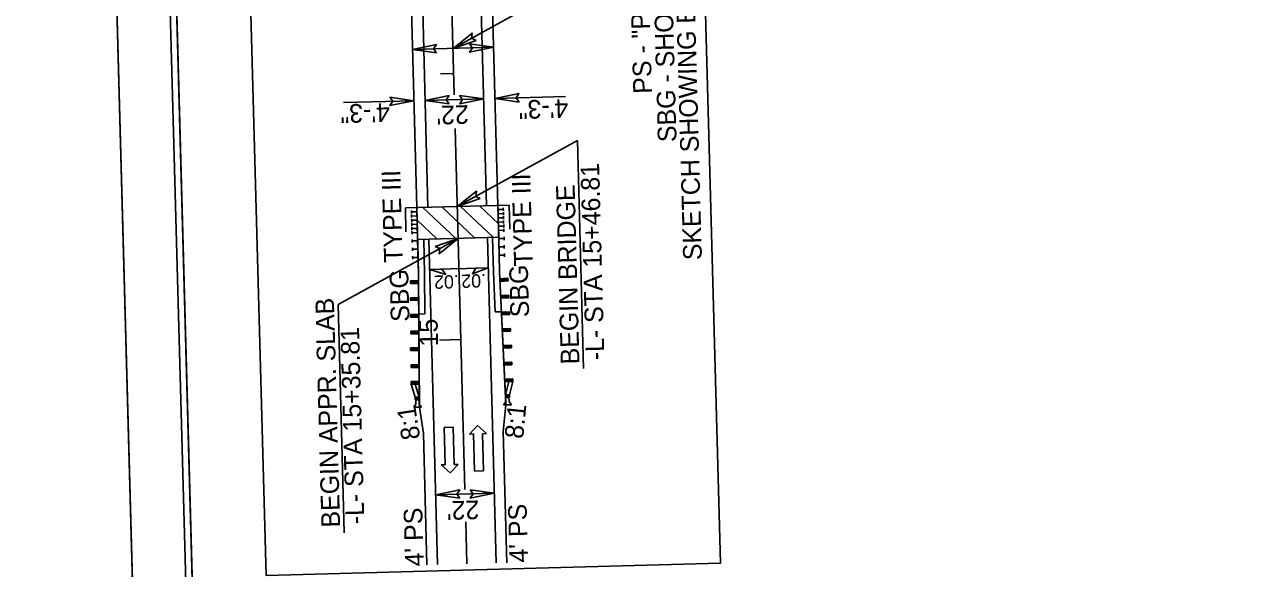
# Model space of a CAD drawing. Extents: x 1835283 to 1836442, y 993567 to 997230.
# Drawn here: x 1835301.2 to 1835759.8, y 993870.9 to 994075.4 of the extents above; entities that cross this region are included whole.
import ezdxf

# ---------------------------------------------------------------- set-up
doc = ezdxf.new("R2010")
doc.units = 0
for name, color, linetype in [('Prop Approach Slab', 7, 'Continuous'), ('Prop Approach Slab Hatching', 7, 'Continuous'), ('Prop Dimension', 7, 'Continuous'), ('Prop EOT', 7, 'Continuous'), ('Prop Guardrail', 7, 'Continuous'), ('Prop Guardrail Anchor Unit CELL', 7, 'Continuous'), ('Prop Horizontal Alignment', 7, 'Continuous'), ('Prop Horizontal Alignment Tick Label', 7, 'Continuous'), ('Prop Horizontal Alignment Tick Large', 7, 'Continuous'), ('Prop Horizontal Alignment Tick Small', 7, 'Continuous'), ('Prop Lane Arrow CELL', 7, 'Continuous'), ('Prop Lane Lines', 7, 'Continuous'), ('Prop Paved Shoulder', 7, 'Continuous'), ('Prop Roadway Bridge', 7, 'Continuous'), ('Prop SBG', 7, 'Continuous'), ('Prop Structure Anchor Unit CELL', 7, 'Continuous'), ('Prop Superelevation  Arrow CELL', 7, 'Continuous'), ('Prop Terminator CELL', 7, 'Continuous'), ('Sheet Clip Boundary CELL', 7, 'Continuous'), ('Sheet Cutting Line CELL', 7, 'Continuous'), ('Sheet Layout Plan Border', 7, 'Continuous'), ('Sheet Plan CELL', 7, 'Continuous'), ('Sheet Plan Layout CELL', 7, 'Continuous'), ('Sheet Plot Border Inside CELL', 7, 'Continuous'), ('Sheet Plot Border Outside CELL', 7, 'Continuous')]:
    doc.layers.add(name, color=color, linetype=linetype)

msp = doc.modelspace()

# ---------------------------------------------------------------- linework, layer by layer
at = {"layer": 'Prop Approach Slab'}
for p, q in [((1835448.84, 993994.6), (1835448.52, 994006.6)), ((1835479.33, 993995.42), (1835479.01, 994007.41)), ((1835479.33, 993995.42), (1835448.84, 993994.6))]:
    msp.add_line(p, q, dxfattribs=at)
at = {"layer": 'Prop Approach Slab Hatching'}
for p, q in [((1835450.85, 994006.66), (1835463.2, 993994.99)), ((1835457.93, 994006.85), (1835470.28, 993995.18)), ((1835465.01, 994007.04), (1835477.36, 993995.37)), ((1835472.09, 994007.23), (1835479.2, 994000.51)), ((1835448.65, 994001.86), (1835456.12, 993994.8))]:
    msp.add_line(p, q, dxfattribs=at)
at = {"layer": 'Prop Dimension'}
for p, q in [((1835462.17, 994066.44), (1835494.43, 994084.16)), ((1835477.42, 994066.84), (1835446.93, 994066.03)), ((1835504.36, 994048.28), (1835477.94, 994047.57)), ((1835447.45, 994046.75), (1835421.03, 994046.05)), ((1835473.69, 994047.46), (1835451.69, 994046.87)), ((1835508.87, 994031.8), (1835463.77, 994007.01)), ((1835511.21, 993946.11), (1835508.87, 994031.8)), ((1835464.09, 993995.01), (1835418.99, 993970.21)), ((1835421.33, 993884.43), (1835418.99, 993970.21)), ((1835477.65, 993899.27), (1835455.66, 993898.68))]:
    msp.add_line(p, q, dxfattribs=at)
msp.add_lwpolyline([(1835549.77, 994346.04), (1835562.69, 993873.01), (1835392.04, 993868.35), (1835379.12, 994341.38)], close=True, dxfattribs=at)
at = {"layer": 'Prop EOT'}
for p, q in [((1835456.36, 993872.46), (1835453.09, 993994.72)), ((1835478.36, 993873.05), (1835475.08, 993995.31))]:
    msp.add_line(p, q, dxfattribs=at)
at = {"layer": 'Prop Guardrail'}
msp.add_line((1835449.02, 993987.86), (1835449.19, 993981.61), dxfattribs=at)
msp.add_lwpolyline([(1835479.68, 993982.42), (1835479.51, 993988.67)], dxfattribs=at)
at = {"layer": 'Prop Guardrail Anchor Unit CELL'}
for p, q in [((1835449.21, 993979.06), (1835446.21, 993979.04)), ((1835447.71, 993978.05), (1835446.21, 993979.04)), ((1835446.21, 993979.04), (1835446.22, 993978.04)), ((1835446.22, 993978.04), (1835447.71, 993979.05)), ((1835447.71, 993978.05), (1835449.21, 993979.06)), ((1835447.71, 993979.05), (1835447.71, 993978.05)), ((1835447.71, 993979.05), (1835449.21, 993978.06)), ((1835449.19, 993981.61), (1835449.51, 993934.86)), ((1835449.21, 993979.06), (1835449.21, 993978.06)), ((1835479.68, 993982.42), (1835481.87, 993935.72)), ((1835479.8, 993979.88), (1835482.79, 993980.02)), ((1835479.8, 993979.88), (1835479.85, 993978.89)), ((1835481.34, 993978.96), (1835479.8, 993979.88)), ((1835481.3, 993979.95), (1835479.85, 993978.89)), ((1835479.85, 993978.89), (1835482.84, 993979.03)), ((1835479.85, 993978.89), (1835481.34, 993978.96)), ((1835481.3, 993979.95), (1835481.34, 993978.96)), ((1835482.84, 993979.03), (1835481.3, 993979.95)), ((1835481.34, 993978.96), (1835482.79, 993980.02)), ((1835482.79, 993980.02), (1835482.84, 993979.03)), ((1835449.21, 993978.06), (1835446.22, 993978.04)), ((1835449.21, 993978.06), (1835447.71, 993978.05)), ((1835449.25, 993972.76), (1835446.2, 993972.74)), ((1835446.2, 993971.74), (1835447.72, 993972.75)), ((1835447.73, 993971.75), (1835446.2, 993972.74)), ((1835446.2, 993972.74), (1835446.2, 993971.74)), ((1835449.26, 993971.76), (1835446.2, 993971.74)), ((1835447.72, 993972.75), (1835447.73, 993971.75)), ((1835447.72, 993972.75), (1835449.26, 993971.76)), ((1835449.25, 993972.76), (1835447.73, 993971.75)), ((1835480.09, 993973.59), (1835483.14, 993973.73)), ((1835480.09, 993973.59), (1835481.66, 993972.66)), ((1835481.62, 993973.66), (1835480.14, 993972.59)), ((1835480.14, 993972.59), (1835483.19, 993972.73)), ((1835481.62, 993973.66), (1835481.66, 993972.66)), ((1835483.19, 993972.73), (1835481.62, 993973.66)), ((1835481.66, 993972.66), (1835483.14, 993973.73)), ((1835483.14, 993973.73), (1835483.19, 993972.73)), ((1835449.29, 993966.46), (1835446.25, 993966.44)), ((1835446.25, 993965.44), (1835447.77, 993966.45)), ((1835447.78, 993965.45), (1835446.25, 993966.44)), ((1835446.25, 993966.44), (1835446.25, 993965.44)), ((1835449.3, 993965.46), (1835446.25, 993965.44)), ((1835447.77, 993966.45), (1835447.78, 993965.45)), ((1835447.77, 993966.45), (1835449.3, 993965.46)), ((1835449.29, 993966.46), (1835447.78, 993965.45)), ((1835480.39, 993967.3), (1835483.43, 993967.44)), ((1835480.39, 993967.3), (1835481.96, 993966.37)), ((1835481.91, 993967.37), (1835480.43, 993966.3)), ((1835480.43, 993966.3), (1835483.48, 993966.44)), ((1835481.91, 993967.37), (1835481.96, 993966.37)), ((1835483.48, 993966.44), (1835481.91, 993967.37)), ((1835481.96, 993966.37), (1835483.43, 993967.44)), ((1835483.43, 993967.44), (1835483.48, 993966.44)), ((1835480.68, 993961), (1835483.71, 993961.14)), ((1835480.68, 993961), (1835480.73, 993960)), ((1835480.68, 993961), (1835482.25, 993960.07)), ((1835482.2, 993961.07), (1835480.73, 993960)), ((1835482.2, 993961.07), (1835482.25, 993960.07)), ((1835483.76, 993960.14), (1835482.2, 993961.07)), ((1835482.25, 993960.07), (1835483.71, 993961.14)), ((1835483.71, 993961.14), (1835483.76, 993960.14)), ((1835449.34, 993960.16), (1835446.3, 993960.14)), ((1835447.82, 993959.15), (1835446.3, 993960.14)), ((1835446.3, 993960.14), (1835446.31, 993959.14)), ((1835446.31, 993959.14), (1835447.82, 993960.15)), ((1835449.34, 993959.16), (1835446.31, 993959.14)), ((1835449.34, 993960.16), (1835447.82, 993959.15)), ((1835447.82, 993960.15), (1835447.82, 993959.15)), ((1835447.82, 993960.15), (1835449.34, 993959.16)), ((1835449.34, 993960.16), (1835449.34, 993959.16)), ((1835480.73, 993960), (1835483.76, 993960.14)), ((1835449.38, 993953.86), (1835446.24, 993953.84)), ((1835447.82, 993952.85), (1835446.24, 993953.84)), ((1835446.24, 993953.84), (1835446.25, 993952.84)), ((1835446.25, 993952.84), (1835447.81, 993953.85)), ((1835449.39, 993952.86), (1835446.25, 993952.84)), ((1835447.81, 993953.85), (1835447.82, 993952.85)), ((1835447.81, 993953.85), (1835449.39, 993952.86)), ((1835449.38, 993953.86), (1835447.82, 993952.85)), ((1835480.98, 993954.71), (1835484.11, 993954.85)), ((1835480.98, 993954.71), (1835482.59, 993953.78)), ((1835482.54, 993954.78), (1835481.02, 993953.71)), ((1835481.02, 993953.71), (1835484.16, 993953.85)), ((1835482.54, 993954.78), (1835482.59, 993953.78)), ((1835484.16, 993953.85), (1835482.54, 993954.78)), ((1835482.59, 993953.78), (1835484.11, 993954.85)), ((1835484.11, 993954.85), (1835484.16, 993953.85)), ((1835449.42, 993947.56), (1835446.42, 993947.54)), ((1835447.93, 993946.55), (1835446.42, 993947.54)), ((1835446.42, 993947.54), (1835446.43, 993946.54)), ((1835446.43, 993946.54), (1835447.92, 993947.55)), ((1835447.92, 993947.55), (1835447.93, 993946.55)), ((1835447.92, 993947.55), (1835449.43, 993946.56)), ((1835449.42, 993947.56), (1835447.93, 993946.55)), ((1835481.27, 993948.41), (1835484.27, 993948.55)), ((1835481.27, 993948.41), (1835482.82, 993947.48)), ((1835482.77, 993948.48), (1835481.32, 993947.41)), ((1835481.32, 993947.41), (1835484.31, 993947.55)), ((1835482.77, 993948.48), (1835482.82, 993947.48)), ((1835484.31, 993947.55), (1835482.77, 993948.48)), ((1835482.82, 993947.48), (1835484.27, 993948.55)), ((1835484.27, 993948.55), (1835484.31, 993947.55)), ((1835449.43, 993946.56), (1835446.43, 993946.54)), ((1835481.57, 993942.12), (1835484.63, 993942.26)), ((1835483.1, 993942.19), (1835481.61, 993941.12)), ((1835483.1, 993942.19), (1835483.14, 993941.19)), ((1835484.67, 993941.26), (1835483.1, 993942.19)), ((1835483.14, 993941.19), (1835484.63, 993942.26)), ((1835484.63, 993942.26), (1835484.67, 993941.26)), ((1835449.46, 993941.26), (1835446.4, 993941.24)), ((1835447.94, 993940.25), (1835446.4, 993941.24)), ((1835446.4, 993941.24), (1835446.41, 993940.24)), ((1835446.41, 993940.24), (1835447.93, 993941.25)), ((1835449.47, 993940.26), (1835446.41, 993940.24)), ((1835446.41, 993940.24), (1835448, 993935.35)), ((1835447.93, 993941.25), (1835447.94, 993940.25)), ((1835447.93, 993941.25), (1835449.47, 993940.26)), ((1835449.46, 993941.26), (1835447.94, 993940.25)), ((1835447.94, 993940.25), (1835449.5, 993935.36)), ((1835481.57, 993942.12), (1835483.14, 993941.19)), ((1835481.61, 993941.12), (1835484.67, 993941.26)), ((1835483.14, 993941.19), (1835481.84, 993936.22)), ((1835484.67, 993941.26), (1835483.34, 993936.29)), ((1835449.5, 993935.36), (1835448, 993935.35)), ((1835448, 993935.35), (1835448.01, 993934.85)), ((1835449.51, 993934.36), (1835448, 993935.35)), ((1835448, 993935.35), (1835448.01, 993934.35)), ((1835448.01, 993934.35), (1835449.5, 993935.36)), ((1835449.51, 993934.36), (1835448.01, 993934.35)), ((1835448.21, 993934.8), (1835448.82, 993934.81)), ((1835448.26, 993932.75), (1835448.21, 993934.8)), ((1835448.82, 993934.81), (1835449.43, 993934.82)), ((1835449.43, 993934.82), (1835449.48, 993932.78)), ((1835482, 993933.65), (1835481.17, 993932.45)), ((1835481.84, 993936.22), (1835483.34, 993936.29)), ((1835483.39, 993935.29), (1835481.84, 993936.22)), ((1835481.89, 993935.22), (1835483.34, 993936.29)), ((1835481.89, 993935.22), (1835483.39, 993935.29)), ((1835482.55, 993935.71), (1835481.94, 993935.69)), ((1835481.94, 993935.69), (1835482, 993933.65)), ((1835483.16, 993935.73), (1835482.55, 993935.71)), ((1835483.22, 993933.69), (1835483.16, 993935.73)), ((1835484.11, 993932.53), (1835483.22, 993933.69)), ((1835483.34, 993936.29), (1835483.36, 993935.79)), ((1835483.34, 993936.29), (1835483.39, 993935.29)), ((1835447.43, 993931.55), (1835448.26, 993932.75)), ((1835450.37, 993931.62), (1835447.43, 993931.55)), ((1835449.48, 993932.78), (1835450.37, 993931.62)), ((1835481.17, 993932.45), (1835484.11, 993932.53))]:
    msp.add_line(p, q, dxfattribs=at)
at = {"layer": 'Prop Horizontal Alignment'}
for p, q in [((1835462.64, 994049.02), (1835456.94, 994261.82)), ((1835466.61, 993900.67), (1835462.98, 994036.35)), ((1835467.36, 993872.75), (1835466.94, 993888.5))]:
    msp.add_line(p, q, dxfattribs=at)
at = {"layer": 'Prop Horizontal Alignment Tick Large'}
msp.add_line((1835465.1, 993957.02), (1835457.11, 993956.81), dxfattribs=at)
at = {"layer": 'Prop Horizontal Alignment Tick Small'}
msp.add_line((1835462.43, 994056.99), (1835457.43, 994056.85), dxfattribs=at)
at = {"layer": 'Prop Lane Arrow CELL'}
for p, q in [((1835458.88, 993923.96), (1835462.18, 993924.05)), ((1835459.26, 993909.97), (1835458.88, 993923.96)), ((1835462.18, 993924.05), (1835462.56, 993910.06)), ((1835468.41, 993921.49), (1835471.42, 993924.73)), ((1835471.42, 993924.73), (1835474.71, 993921.67)), ((1835469.91, 993921.53), (1835468.41, 993921.49)), ((1835470.29, 993907.54), (1835469.91, 993921.53)), ((1835474.71, 993921.67), (1835473.21, 993921.62)), ((1835473.21, 993921.62), (1835473.59, 993907.63)), ((1835464.06, 993910.1), (1835461.05, 993906.86)), ((1835462.56, 993910.06), (1835464.06, 993910.1)), ((1835457.76, 993909.93), (1835459.26, 993909.97)), ((1835461.05, 993906.86), (1835457.76, 993909.93)), ((1835473.59, 993907.63), (1835470.29, 993907.54))]:
    msp.add_line(p, q, dxfattribs=at)
at = {"layer": 'Prop Paved Shoulder'}
for p, q in [((1835448.84, 993994.6), (1835449.19, 993981.61)), ((1835479.33, 993995.42), (1835479.68, 993982.42)), ((1835449.19, 993981.61), (1835449.53, 993931.6)), ((1835479.68, 993982.42), (1835482.02, 993932.47)), ((1835451.62, 993966.67), (1835449.29, 993966.6)), ((1835480.38, 993967.44), (1835478.05, 993967.37)), ((1835451.05, 993921.64), (1835449.53, 993931.6)), ((1835481.04, 993922.45), (1835482.02, 993932.47)), ((1835452.37, 993872.35), (1835451.05, 993921.64)), ((1835482.36, 993873.15), (1835481.04, 993922.45))]:
    msp.add_line(p, q, dxfattribs=at)
at = {"layer": 'Prop Roadway Bridge'}
for p, q in [((1835448.52, 994006.6), (1835443.44, 994196.53)), ((1835452.77, 994006.71), (1835447.68, 994196.64)), ((1835474.76, 994007.3), (1835469.68, 994197.23)), ((1835479.01, 994007.41), (1835473.92, 994197.35)), ((1835483.26, 994007.53), (1835444.27, 994006.48)), ((1835444.51, 993997.49), (1835444.27, 994006.48)), ((1835483.5, 993998.53), (1835483.26, 994007.53))]:
    msp.add_line(p, q, dxfattribs=at)
at = {"layer": 'Prop SBG'}
for p, q in [((1835451.17, 993994.67), (1835451.52, 993981.67)), ((1835477.35, 993982.36), (1835477, 993995.36)), ((1835451.52, 993981.67), (1835451.62, 993966.67)), ((1835478.05, 993967.37), (1835477.35, 993982.36))]:
    msp.add_line(p, q, dxfattribs=at)
at = {"layer": 'Prop Structure Anchor Unit CELL'}
for p, q in [((1835448.52, 994006.6), (1835449.02, 993987.86)), ((1835479.01, 994007.41), (1835479.51, 993988.67)), ((1835481.04, 994006.48), (1835481.07, 994005.33)), ((1835446.55, 994005.56), (1835446.58, 994004.41)), ((1835448.56, 994005.04), (1835446.56, 994004.98)), ((1835446.59, 994003.99), (1835446.62, 994002.85)), ((1835448.61, 994003.47), (1835446.61, 994003.42)), ((1835446.63, 994002.43), (1835446.66, 994001.29)), ((1835448.65, 994001.91), (1835446.65, 994001.86)), ((1835479.05, 994005.85), (1835481.05, 994005.91)), ((1835479.09, 994004.29), (1835481.09, 994004.34)), ((1835479.14, 994002.73), (1835481.14, 994002.78)), ((1835481.08, 994004.92), (1835481.11, 994003.77)), ((1835481.12, 994003.36), (1835481.15, 994002.21)), ((1835481.16, 994001.79), (1835481.19, 994000.65)), ((1835446.67, 994000.87), (1835446.7, 993999.72)), ((1835448.69, 994000.35), (1835446.69, 994000.3)), ((1835446.72, 993999.31), (1835446.75, 993998.16)), ((1835448.73, 993998.79), (1835446.73, 993998.74)), ((1835446.76, 993997.75), (1835446.79, 993996.6)), ((1835448.77, 993997.23), (1835446.77, 993997.17)), ((1835479.18, 994001.17), (1835481.18, 994001.22)), ((1835479.22, 993999.61), (1835481.22, 993999.66)), ((1835479.26, 993998.04), (1835481.26, 993998.1)), ((1835481.2, 994000.23), (1835481.23, 993999.09)), ((1835481.25, 993998.67), (1835481.28, 993997.52)), ((1835446.84, 993994.62), (1835446.87, 993993.48)), ((1835448.86, 993994.1), (1835446.86, 993994.05)), ((1835479.35, 993994.92), (1835481.34, 993994.97)), ((1835481.33, 993995.55), (1835481.36, 993994.4)), ((1835446.92, 993991.5), (1835446.96, 993990.35)), ((1835448.94, 993990.98), (1835446.94, 993990.93)), ((1835447.01, 993988.37), (1835447.04, 993987.23)), ((1835479.43, 993991.8), (1835481.43, 993991.85)), ((1835479.51, 993988.67), (1835481.51, 993988.73)), ((1835481.41, 993992.42), (1835481.44, 993991.28)), ((1835481.5, 993989.3), (1835481.53, 993988.15)), ((1835449.02, 993987.86), (1835447.02, 993987.8))]:
    msp.add_line(p, q, dxfattribs=at)
at = {"layer": 'Prop Superelevation  Arrow CELL'}
for p, q in [((1835453.41, 993983.32), (1835465.4, 993983.65)), ((1835475.4, 993983.92), (1835463.4, 993983.59))]:
    msp.add_line(p, q, dxfattribs=at)
for points in [[(1835453.41, 993983.32), (1835459.46, 993981.49), (1835458.03, 993983.45)], [(1835475.4, 993983.92), (1835469.46, 993981.76), (1835470.78, 993983.8)]]:
    msp.add_lwpolyline(points, close=True, dxfattribs=at)
at = {"layer": 'Prop Terminator CELL'}
for points in [[(1835470.81, 994069.41), (1835462.17, 994066.44), (1835469.34, 994072.2), (1835469.1, 994070.24)], [(1835455.97, 994064.72), (1835446.93, 994066.03), (1835455.93, 994067.87), (1835454.83, 994066.24)], [(1835468.38, 994068.15), (1835477.42, 994066.84), (1835468.42, 994065), (1835469.52, 994066.63)], [(1835438.41, 994048.06), (1835447.45, 994046.75), (1835438.44, 994044.91), (1835439.55, 994046.54)], [(1835460.73, 994045.56), (1835451.69, 994046.87), (1835460.7, 994048.71), (1835459.59, 994047.08)], [(1835464.65, 994048.77), (1835473.69, 994047.46), (1835464.68, 994045.62), (1835465.79, 994047.25)], [(1835486.97, 994046.26), (1835477.94, 994047.57), (1835486.94, 994049.41), (1835485.83, 994047.78)], [(1835472.4, 994009.98), (1835463.77, 994007.01), (1835470.93, 994012.77), (1835470.69, 994010.81)], [(1835455.46, 993992.03), (1835464.09, 993995.01), (1835456.93, 993989.25), (1835457.17, 993991.2)], [(1835464.7, 993897.37), (1835455.66, 993898.68), (1835464.67, 993900.52), (1835463.56, 993898.89)], [(1835468.62, 993900.57), (1835477.65, 993899.27), (1835468.65, 993897.42), (1835469.76, 993899.05)]]:
    msp.add_lwpolyline(points, close=True, dxfattribs=at)
at = {"layer": 'Sheet Clip Boundary CELL'}
msp.add_lwpolyline([(1836414.25, 993881.51), (1836374.18, 995348.6), (1835535.98, 995325.71), (1835542.09, 995102.18), (1835330.68, 995096.4), (1835364.64, 993852.84)], close=True, dxfattribs=at)
msp.add_lwpolyline([(1836414.25, 993881.51), (1836374.18, 995348.6), (1835535.98, 995325.71), (1835542.09, 995102.18), (1835330.68, 995096.4), (1835364.64, 993852.84)], close=True, dxfattribs=at)
at = {"layer": 'Sheet Cutting Line CELL'}
msp.add_line((1835301.2, 995351.94), (1835347.16, 993669.07), dxfattribs=at)
at = {"layer": 'Sheet Layout Plan Border'}
msp.add_lwpolyline([(1836414.25, 993881.51), (1836374.18, 995348.6), (1835535.98, 995325.71), (1835542.09, 995102.18), (1835330.68, 995096.4), (1835364.64, 993852.84)], close=True, dxfattribs=at)
msp.add_lwpolyline([(1836414.25, 993881.51), (1836374.18, 995348.6), (1835535.98, 995325.71), (1835542.09, 995102.18), (1835330.68, 995096.4), (1835364.64, 993852.84)], close=True, dxfattribs=at)
at = {"layer": 'Sheet Plan CELL'}
for points in [[(1835324.15, 995335.59), (1835365.1, 993836.11), (1836414.7, 993864.77), (1836373.75, 995364.23)], [(1836414.7, 993864.77), (1835365.12, 993836.09), (1835329.59, 995135.59), (1835479.6, 995139.7), (1835474.15, 995339.66), (1836373.75, 995364.23)]]:
    msp.add_lwpolyline(points, close=True, dxfattribs=at)
at = {"layer": 'Sheet Plan Layout CELL'}
msp.add_lwpolyline([(1835365.12, 993836.1), (1836414.7, 993864.79), (1836373.75, 995364.23), (1835535.55, 995341.34), (1835542.09, 995102.18), (1835330.68, 995096.4)], close=True, dxfattribs=at)
at = {"layer": 'Sheet Plot Border Inside CELL'}
msp.add_lwpolyline([(1836421.41, 993711.41), (1836375.91, 995376.78), (1835321.32, 995347.99), (1835366.8, 993682.61)], close=True, dxfattribs=at)
at = {"layer": 'Sheet Plot Border Outside CELL'}
msp.add_lwpolyline([(1836441.75, 993698.96), (1836395.79, 995381.84), (1835301.2, 995351.94), (1835347.16, 993669.07)], close=True, dxfattribs=at)

# ---------------------------------------------------------------- texts
at = {"layer": 'Prop Dimension'}
for s, rotation, p in [('SKETCH SHOWING BRIDGE/PAVEMENT RELATIONSHIP', 91.5643, (1835555.65, 993986.91)), ('SBG - SHOULDER BERM GUTTER', 91.5643, (1835546.13, 994031.3)), ('PS - "PAVED SHOULDER"', 91.5643, (1835536.89, 994049.46)), ('4\'-3"', 181.5645, (1835438.38, 994045.85)), ("22'", 181.5645, (1835468, 994045.12)), ('4\'-3"', 181.5645, (1835505.39, 994047.38)), ('-L- STA 15+46.81', 91.5643, (1835519.04, 993949.31)), ('BEGIN BRIDGE', 91.5643, (1835509.68, 993947.77)), ('BEGIN APPR. SLAB', 91.5643, (1835419.78, 993886.46)), ('-L- STA 15+35.81', 91.5643, (1835428.88, 993887.69)), ("22'", 181.5645, (1835471.94, 993896.56))]:
    msp.add_text(s, height=7, rotation=rotation, dxfattribs=at).set_placement(p)
at = {"layer": 'Prop Guardrail Anchor Unit CELL'}
for p in [(1835443.3, 993985.97), (1835492.12, 993984.66)]:
    msp.add_text('TYPE III', height=7, rotation=91.5645, dxfattribs=at).set_placement(p)
at = {"layer": 'Prop Horizontal Alignment Tick Label'}
msp.add_text('15', height=7, rotation=91.5338, dxfattribs=at).set_placement((1835456.61, 993954.5))
at = {"layer": 'Prop Lane Lines'}
for p in [(1835464.27, 993981.3), (1835474.5, 993981.66)]:
    msp.add_text('.02', height=5, rotation=181.5643, dxfattribs=at).set_placement(p)
at = {"layer": 'Prop Terminator CELL'}
for s, rotation, p in [('SBG', 91.5338, (1835490.77, 993965.47)), ('SBG', 91.5338, (1835445.84, 993963.77)), ('8:1', 98.6603, (1835449.88, 993919.85)), ('8:1', 84.4074, (1835488.48, 993919.5)), ("4' PS", 91.5338, (1835451.19, 993871.83)), ("4' PS", 91.5338, (1835490.37, 993873.3))]:
    msp.add_text(s, height=7, rotation=rotation, dxfattribs=at).set_placement(p)

doc.saveas('drawing.dxf')
